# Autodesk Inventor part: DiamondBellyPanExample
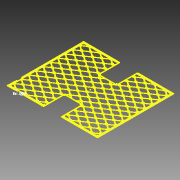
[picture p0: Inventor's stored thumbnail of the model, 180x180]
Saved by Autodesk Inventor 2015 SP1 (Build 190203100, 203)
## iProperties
Created: 2016-01
Part Number: DiamondBellyPanExample
Material: Aluminum 6061
Document SubType Name: Sheet Metal
Designer: User
Density: 2.7 g/cm^3
Sheet Metal Rule: Default
Appearance: Aluminum - Flat
Mass: 806.053 g
Surface Area: 2862.53 cm^2
Volume: 298.538 cm^3
Author: User
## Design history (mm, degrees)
node "Face1"
  sketch "Sketch1"
    geometry: L1 (-330.2, 279.4)-(330.2, 279.4); L2 (330.2, 279.4)-(330.2, -279.4); L3 (330.2, -279.4)-(-330.2, -279.4); L4 (-330.2, -279.4)-(-330.2, 279.4); L5 (-330.2, 279.4)-(330.2, -279.4); L6 (330.2, 279.4)-(-330.2, -279.4); 1 further point
    constraints: 12 end point, 2 midpoint, 2 parallel, 1 horizontal, 1 perpendicular
    dimensions: "d0" = 660.4 distance of L2.end L3.end; "d1" = 558.8 distance of L1.end L2.end
sketch "Sketch2"
  geometry: L1 (-330.2, -279.4)-(-330.2, 279.4) reference; L2 (330.2, -279.4)-(-330.2, -279.4) reference; L3 (330.2, 279.4)-(330.2, -279.4) reference; L4 (-330.2, 279.4)-(330.2, 279.4) reference; L5 (-313.231, -240.03)-(-277.812, -263.831); L6 (-277.812, -263.831)-(-242.394, -240.03); L7 (-242.394, -240.03)-(-277.812, -216.229); L8 (-277.812, -216.229)-(-313.231, -240.03); L9 (-240.26, -238.596)-(-275.678, -214.794); L10 (-238.125, -237.161)-(-273.543, -213.36); L11 (-238.125, -237.161)-(-202.707, -213.36); L12 (-202.707, -213.36)-(-238.125, -189.559); L13 (-238.125, -189.559)-(-273.543, -213.36); L14 (-242.394, -240.03)-(-238.125, -237.161); L15 (-277.812, -216.229)-(-273.543, -213.36); L16 (-313.231, -186.69)-(-277.812, -210.491); L17 (-277.812, -210.491)-(-242.394, -186.69); L18 (-242.394, -186.69)-(-277.812, -162.889); L19 (-277.812, -162.889)-(-313.231, -186.69); L20 (-240.26, -185.256)-(-275.678, -161.454); L21 (-238.125, -183.821)-(-273.543, -160.02); L22 (-238.125, -183.821)-(-202.707, -160.02); L23 (-202.707, -160.02)-(-238.125, -136.219); L24 (-238.125, -136.219)-(-273.543, -160.02); L25 (-242.394, -186.69)-(-238.125, -183.821); L26 (-277.812, -162.889)-(-273.543, -160.02); L27 (-313.231, -133.35)-(-277.812, -157.151); L28 (-277.812, -157.151)-(-242.394, -133.35); L29 (-242.394, -133.35)-(-277.812, -109.549); L30 (-277.812, -109.549)-(-313.231, -133.35); L31 (-240.26, -131.916)-(-275.678, -108.114); L32 (-238.125, -130.481)-(-273.543, -106.68); L33 (-238.125, -130.481)-(-202.707, -106.68); L34 (-202.707, -106.68)-(-238.125, -82.879); L35 (-238.125, -82.879)-(-273.543, -106.68); L36 (-242.394, -133.35)-(-238.125, -130.481); L37 (-277.812, -109.549)-(-273.543, -106.68); L38 (-313.231, -80.01)-(-277.812, -103.811); L39 (-277.812, -103.811)-(-242.394, -80.01); L40 (-242.394, -80.01)-(-277.812, -56.209); L41 (-277.812, -56.209)-(-313.231, -80.01); L42 (-240.26, -78.576)-(-275.678, -54.774); L43 (-238.125, -77.141)-(-273.543, -53.34); L44 (-238.125, -77.141)-(-202.707, -53.34); L45 (-202.707, -53.34)-(-238.125, -29.539); L46 (-238.125, -29.539)-(-273.543, -53.34); L47 (-242.394, -80.01)-(-238.125, -77.141); L48 (-277.812, -56.209)-(-273.543, -53.34); L49 (-313.231, -26.67)-(-277.812, -50.471); L50 (-277.812, -50.471)-(-242.394, -26.67); L51 (-242.394, -26.67)-(-277.812, -2.869); L52 (-277.812, -2.869)-(-313.231, -26.67); L53 (-240.26, -25.236)-(-275.678, -1.434); L54 (-238.125, -23.801)-(-273.543, 0); L55 (-238.125, -23.801)-(-202.707, 0); L56 (-202.707, 0)-(-238.125, 23.801); L57 (-238.125, 23.801)-(-273.543, 0); L58 (-242.394, -26.67)-(-238.125, -23.801); L59 (-277.812, -2.869)-(-273.543, 0); L60 (-313.231, 26.67)-(-277.812, 2.869); L61 (-277.812, 2.869)-(-242.394, 26.67); L62 (-242.394, 26.67)-(-277.812, 50.471); L63 (-277.812, 50.471)-(-313.231, 26.67); L64 (-240.26, 28.104)-(-275.678, 51.906)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; A1 r 2.286 centre (-266.043, -264.414) between (-267.318, -262.517) and (-266.043, -266.7); A2 r 2.286 centre (-210.207, -264.414) between (-210.207, -266.7) and (-208.932, -262.517); A3 r 2.286 centre (-289.582, -264.414) between (-289.582, -266.7) and (-288.307, -262.517); A4 r 2.286 centre (-315.214, -264.414) between (-317.5, -264.414) and (-315.214, -266.7); A5 r 2.286 centre (-315.214, -247.189) between (-313.939, -245.292) and (-317.5, -247.189); A6 r 2.286 centre (-315.214, -232.871) between (-317.5, -232.871) and (-313.939, -234.768); A7 r 2.286 centre (-315.214, -193.849) between (-313.939, -191.952) and (-317.5, -193.849); A8 r 2.286 centre (-238.125, -245.653) between (-236.85, -243.756) and (-239.4, -243.756); A9 r 2.286 centre (-286.18, -213.36) between (-284.905, -215.257) and (-284.905, -211.463); 3 further points
  constraints: 1808 end point, 343 point on line, 18 point on circle, 18 tangent, 9 centre point, 6 equal length, 6 perpendicular, 5 parallel, 4 equal radius, 4 vertical, 2 collinear, 2 horizontal, 2 horizontal alignment, 2 midpoint, 1 vertical alignment, 1683 other
  dimensions: "d15" = 4.7625 distance between parallel lines of L7 L10; "d62" = 53.34 distance of L5.start L16.start (derived); "d69" = 79.375 distance of L6.end L115.end (derived); "d74" = 4.7625 distance between parallel lines of L46 L50 (derived); "d75" = 4.7625 distance between parallel lines of L510 L367 (derived); "d85" = 53.34 distance of L11.end L895.end (derived); "d88" = 79.375 distance of L11.end L898.start (derived); "d91" = 2.286 radius of A1; "d92" = 2.286 radius of A2; "d93" = 2.286 radius of A3; "d94" = 2.286 radius of A8 (derived); "d95" = 2.286 radius of A9 (derived)
cut "Cut1" sketch "Sketch2" dims "d35" = 3.175 (= Thickness), "d36" = 0
feature "Corner Round3" dims "d96" = 2.286
mirror "Mirror3"
mirror "Mirror4"
sketch "Sketch4"
  geometry: L1 (330.2, -279.4)-(-330.2, -279.4) reference; L2 (63.5, -279.4)-(-63.5, -279.4); L3 (-63.5, -279.4)-(-63.5, -127); L4 (-63.5, -127)-(63.5, -127); L5 (63.5, -127)-(63.5, -279.4); 2 further points
  constraints: 8 end point, 2 midpoint, 2 parallel, 1 coincident, 1 horizontal, 1 perpendicular, 1 point on line
  dimensions: "d103" = 152.4 distance between parallel lines of L1 L4 (derived); "d104" = 127 distance between parallel lines of L5 L3 (derived)
cut "Cut2" sketch "Sketch4" dims "d105" = 3.175 (derived), "d106" = 0
node "Face2"
  sketch "Sketch5"
    geometry: L1 (-63.5, -279.4)-(-330.2, -279.4) reference; L2 (-63.5, -279.4)-(-63.5, -127); L3 (-63.5, -127)-(0, -127); L4 (0, -127)-(0, -122.238); L5 (0, -122.238)-(-68.263, -122.238); L6 (-68.263, -122.238)-(-68.262, -279.4); L7 (-63.5, -279.4)-(-68.262, -279.4); 1 further point
    constraints: 12 end point, 4 perpendicular, 2 point on line, 1 collinear, 1 vertical, 1 vertical alignment
    dimensions: "d107" = 63.5 distance from line of point (0, 0) L2 (derived); "d108" = 152.4 distance between parallel lines of L1 L3 (derived); "d109" = 4.7625 distance between parallel lines of L6 L2; "d110" = 4.7625 distance between parallel lines of L5 L3 (derived)
mirror "Mirror5"
feature "Corner Round4" dims "d116" = 4.7625
mirror "Mirror6"
feature "Corner Round5" dims "d117" = 6.35
feature "Corner Round6" dims "d118" = 3.175
sketch "Sketch6"
  geometry: L1 (-330.2, -276.225)-(-330.2, 276.225) reference; L2 (-68.262, -279.4)-(-327.025, -279.4) reference; C1 r 2.451 at (-323.85, -273.05); 5 further points
  constraints: 1 centre point
  dimensions: "d119" = 2.4511 radius of C1; "d120" = 6.35 distance from line of L1 C1.centre; "d121" = 6.35 distance from line of L2 C1.centre (derived)
hole "Hole1" sketch "Sketch6" at (-323.85, -273.05) diameter "d122" = 4.9022 (derived); stored, may be unused: countersink angle "d126" = 82 deg, drill point angle "d128" = 118 deg; dims "d123" = 19.05, "d124" = 9.525, "d125" = 6.35, "d127" = 3.175 (derived)
mirror "Mirror7"
mirror "Mirror8"
sketch "Sketch7"
  geometry: L1 (-330.2, -276.225)-(-330.2, 276.225) reference; L2 (-68.262, -279.4)-(-327.025, -279.4) reference; L3 (-317.5, -232.871)-(-317.5, -193.849) reference; L4 (-210.207, -266.7)-(-266.043, -266.7) reference; L5 (-330.2, -215.9)-(-317.5, -215.9); L6 (-266.7, -279.4)-(-266.7, -266.7); L7 (-315.214, -266.7)-(-266.7, -266.7); L8 (-315.214, -266.7)-(-289.582, -266.7) reference; L9 (-317.5, -264.414)-(-317.5, -215.9); L10 (-274.637, -279.4)-(-266.7, -279.4); L11 (-68.262, -279.4)-(-327.025, -279.4) reference; L12 (-266.7, -271.463)-(-266.7, -279.4); L13 (-330.2, -223.838)-(-330.2, -215.9); L14 (-322.262, -215.9)-(-330.2, -215.9); L15 (-321.27, -213.613)-(-321.27, -191.289); L16 (-322.989, -215.9)-(-330.2, -215.9); L17 (-330.2, -215.9)-(-330.2, -223.838); A1 r 7.938 centre (-274.637, -271.463) between (-274.637, -279.4) and (-266.7, -271.463); A2 r 7.938 centre (-322.262, -223.838) between (-322.262, -215.9) and (-330.2, -223.838); A3 r 2.381 centre (-323.652, -213.613) between (-323.331, -215.972) and (-321.27, -213.613); A4 r 7.938 centre (-322.262, -223.838) between (-323.331, -215.972) and (-330.2, -223.838); A5 r 2.381 centre (-323.652, -213.613) between (-323.331, -215.972) and (-322.989, -215.9); 1 further point
  constraints: 22 end point, 14 tangent, 12 point on circle, 9 point on line, 7 collinear, 5 centre point, 2 perpendicular, 1 horizontal, 1 vertical
  dimensions: "d135" = 63.5 distance between parallel lines of L2 L5 (derived); "d136" = 63.5 distance between parallel lines of L1 L6 (derived); "d137" = 7.9375 radius of A1; "d138" = 7.9375 radius of A2 (derived); "d139" = 3.77031 distance between parallel lines of L3 L15; "d140" = 2.38125 radius of A3
cut "Cut3" sketch "Sketch7" dims "d141" = 3.175 (derived), "d142" = 0
workplane "Work Plane1"
mirror "Mirror9"
sketch "Sketch8"
  geometry: L1 (-266.7, -272.189)-(-266.7, -279.4) reference; L2 (-68.262, -279.4)-(-266.7, -279.4) reference; L3 (-264.413, -270.47)-(-229.455, -270.47); L4 (-222.25, -277.882)-(-222.25, -279.4); L5 (-266.7, -272.189)-(-266.7, -279.4); L6 (-266.7, -279.4)-(-222.25, -279.4); L7 (-222.25, -279.4)-(-266.7, -279.4); L8 (-266.7, -279.4)-(-266.7, -272.189); C1 r 2.451 at (-260.35, -273.05) reference; C2 r 2.451 at (-247.65, -273.05) reference; C3 r 2.451 at (-234.95, -273.05) reference; C4 r 2.451 at (-222.25, -273.05) reference; C5 r 2.451 at (-222.25, -273.05); A1 r 2.381 centre (-264.413, -272.852) between (-266.7, -272.189) and (-266.772, -272.531) reference; A2 r 2.381 centre (-264.413, -272.852) between (-264.413, -270.47) and (-266.772, -272.531); A3 r 2.381 centre (-229.455, -272.852) between (-227.082, -273.05) and (-229.455, -270.47); A4 r 4.832 centre (-222.25, -273.05) between (-227.082, -273.05) and (-222.25, -277.882); A5 r 2.381 centre (-264.413, -272.852) between (-264.413, -270.47) and (-266.7, -272.189); 1 further point
  constraints: 12 end point, 8 point on circle, 5 centre point, 4 tangent, 3 collinear, 2 horizontal alignment, 2 perpendicular, 1 coincident, 1 concentric, 1 horizontal, 1 point on line
  dimensions: "d144" = 2.38125 radius of A3 (derived); "d147" = 38.1 distance of C1.centre A4.centre (derived); "d148" = 2.4511 radius of C5 (derived); "d149" = 2.38125 radial gap between concentric circles of A4 C5; "d150" = 38.1 horizontal distance of C1.centre L4.start (derived)
cut "Cut4" sketch "Sketch8" dims "d145" = 3.175 (derived), "d146" = 0
mirror "Mirror10"
sketch "Sketch9"
  geometry: L1 (-330.2, -276.225)-(-330.2, -223.838) reference; L2 (-274.637, -279.4)-(-327.025, -279.4) reference; L3 (-264.413, -270.47)-(-229.455, -270.47) reference; L4 (-222.25, -277.882)-(-222.25, -279.4) reference; L5 (-68.262, -279.4)-(-222.25, -279.4) reference; L6 (-63.5, -274.637)-(-63.5, -131.763) reference; L7 (-58.738, -127)-(58.737, -127) reference; L8 (63.5, -131.763)-(63.5, -274.638) reference; L9 (327.025, -279.4)-(68.263, -279.4) reference; L10 (330.2, 276.225)-(330.2, -276.225) reference; L11 (69.85, 279.4)-(327.025, 279.4) reference; L12 (63.5, 273.05)-(63.5, 131.763) reference; L13 (-58.738, 127)-(58.737, 127) reference; L14 (-63.5, 131.763)-(-63.5, 273.05) reference; L15 (-327.025, 279.4)-(-69.85, 279.4) reference; L16 (-330.2, -171.45)-(-330.2, 276.225) reference; L17 (-330.2, -171.45)-(-328.682, -171.45) reference; L18 (-321.27, -178.655)-(-321.27, -213.613) reference; L19 (-12.267, 122.238)-(12.267, 122.238) reference; L20 (12.267, 122.238)-(32.595, 108.577) reference; L21 (32.595, 104.783)-(1.275, 83.736) reference; L22 (-1.275, 83.736)-(-32.595, 104.783) reference; L23 (-32.595, 108.577)-(-12.267, 122.238) reference; L24 (68.262, 266.7)-(107.293, 266.7) reference; L25 (108.568, 262.517)-(80.65, 243.756) reference; L26 (78.1, 243.756)-(68.262, 250.367) reference; L27 (68.262, 250.367)-(68.262, 266.7) reference; L28 (20.806, 122.238)-(58.569, 122.238) reference; L29 (58.569, 122.238)-(40.963, 110.406) reference; L30 (38.412, 110.406)-(20.806, 122.238) reference; L31 (68.262, 244.629)-(72.282, 241.927) reference; L32 (72.282, 238.133)-(68.262, 235.431) reference; L33 (68.262, 235.431)-(68.262, 244.629) reference; L34 (68.262, 229.693)-(78.1, 236.304) reference; L35 (80.65, 236.304)-(111.97, 215.257) reference; L36 (111.97, 211.463)-(80.65, 190.416) reference; L37 (78.1, 190.416)-(68.263, 197.027) reference; L38 (68.263, 197.027)-(68.262, 229.693) reference; L39 (68.263, 191.289)-(72.282, 188.587) reference; L40 (72.282, 184.793)-(68.263, 182.091) reference; L41 (68.263, 182.091)-(68.263, 191.289) reference; L42 (68.263, 176.353)-(78.1, 182.964) reference; L43 (80.65, 182.964)-(111.97, 161.917) reference; L44 (111.97, 158.123)-(80.65, 137.076) reference; L45 (78.1, 137.076)-(68.263, 143.687) reference; L46 (68.263, 143.687)-(68.263, 176.353) reference; L47 (68.263, 128.751)-(68.263, 137.949) reference; L48 (68.263, 137.949)-(72.282, 135.247) reference; L49 (72.282, 131.453)-(68.263, 128.751) reference; L50 (12.267, -122.238)-(-12.267, -122.238) reference; L51 (-12.267, -122.238)-(-32.595, -108.577) reference; L52 (-32.595, -104.783)-(-1.275, -83.736) reference; L53 (1.275, -83.736)-(32.595, -104.783) reference; L54 (32.595, -108.577)-(12.267, -122.238) reference; L55 (20.806, -122.238)-(38.412, -110.406) reference; L56 (40.963, -110.406)-(58.569, -122.238) reference; L57 (20.806, -122.238)-(58.569, -122.238) reference; L58 (68.263, -128.751)-(72.282, -131.453) reference; L59 (72.282, -135.247)-(68.263, -137.949) reference; L60 (68.263, -128.751)-(68.263, -137.949) reference; L61 (68.263, -143.687)-(78.1, -137.076) reference; L62 (80.65, -137.076)-(111.97, -158.123) reference; L63 (111.97, -161.917)-(80.65, -182.964) reference; L64 (78.1, -182.964)-(68.263, -176.353) reference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; C1 r 2.451 at (-323.85, -273.05) reference; C2 r 2.451 at (-323.85, -260.35) reference; C3 r 2.451 at (-323.85, -247.65) reference; C4 r 2.451 at (-323.85, -234.95) reference; C5 r 2.451 at (-323.85, -222.25) reference; C6 r 2.451 at (-323.85, -171.45) reference; C7 r 2.451 at (-323.85, -158.75) reference; C8 r 2.451 at (-323.85, -146.05) reference; C9 r 2.451 at (-323.85, -133.35) reference; C10 r 2.451 at (-323.85, -120.65) reference; C11 r 2.451 at (-323.85, -107.95) reference; C12 r 2.451 at (-323.85, -95.25) reference; C13 r 2.451 at (-323.85, -82.55) reference; C14 r 2.451 at (-323.85, -69.85) reference; C15 r 2.451 at (-323.85, -57.15) reference; C16 r 2.451 at (-323.85, -44.45) reference; C17 r 2.451 at (-323.85, -31.75) reference; C18 r 2.451 at (-323.85, -19.05) reference; C19 r 2.451 at (-323.85, -6.35) reference; C20 r 2.451 at (-311.15, -273.05) reference; C21 r 2.451 at (-298.45, -273.05) reference; C22 r 2.451 at (-285.75, -273.05) reference; C23 r 2.451 at (-273.05, -273.05) reference; C24 r 2.451 at (-222.25, -273.05) reference; C25 r 2.451 at (-209.55, -273.05) reference; C26 r 2.451 at (-196.85, -273.05) reference; C27 r 2.451 at (-184.15, -273.05) reference; C28 r 2.451 at (-171.45, -273.05) reference; C29 r 2.451 at (-158.75, -273.05) reference; C30 r 2.451 at (-146.05, -273.05) reference; C31 r 2.451 at (-133.35, -273.05) reference; C32 r 2.451 at (-120.65, -273.05) reference; C33 r 2.451 at (-107.95, -273.05) reference; C34 r 2.451 at (-95.25, -273.05) reference; C35 r 2.451 at (-82.55, -273.05) reference; C36 r 2.451 at (-69.85, -273.05) reference; C37 r 2.451 at (-323.85, 273.05) reference; C38 r 2.451 at (-323.85, 260.35) reference; C39 r 2.451 at (-323.85, 247.65) reference; C40 r 2.451 at (-323.85, 234.95) reference; C41 r 2.451 at (-323.85, 222.25) reference; C42 r 2.451 at (-323.85, 209.55) reference; C43 r 2.451 at (-323.85, 196.85) reference; C44 r 2.451 at (-323.85, 184.15) reference; C45 r 2.451 at (-323.85, 171.45) reference; C46 r 2.451 at (-323.85, 158.75) reference; C47 r 2.451 at (-323.85, 146.05) reference; C48 r 2.451 at (-323.85, 133.35) reference; C49 r 2.451 at (-323.85, 120.65) reference; C50 r 2.451 at (-323.85, 107.95) reference; C51 r 2.451 at (-323.85, 95.25) reference; C52 r 2.451 at (-323.85, 82.55) reference; C53 r 2.451 at (-323.85, 69.85) reference; C54 r 2.451 at (-323.85, 57.15) reference; C55 r 2.451 at (-323.85, 44.45) reference; C56 r 2.451 at (-323.85, 31.75) reference; C57 r 2.451 at (-323.85, 19.05) reference; C58 r 2.451 at (-323.85, 6.35) reference; C59 r 2.451 at (-311.15, 273.05) reference; C60 r 2.451 at (-298.45, 273.05) reference; C61 r 2.451 at (-285.75, 273.05) reference; C62 r 2.451 at (-273.05, 273.05) reference; C63 r 2.451 at (-260.35, 273.05) reference; C64 r 2.451 at (-247.65, 273.05) reference; A1 r 2.381 centre (-323.652, -213.613) between (-323.331, -215.972) and (-321.27, -213.613) reference; A2 r 7.938 centre (-322.262, -223.838) between (-323.331, -215.972) and (-330.2, -223.838) reference; A3 r 3.175 centre (-327.025, -276.225) between (-330.2, -276.225) and (-327.025, -279.4) reference; A4 r 7.938 centre (-274.638, -271.462) between (-274.637, -279.4) and (-266.772, -272.531) reference; A5 r 2.381 centre (-264.413, -272.852) between (-264.413, -270.47) and (-266.772, -272.531) reference; A6 r 2.381 centre (-229.455, -272.852) between (-227.082, -273.05) and (-229.455, -270.47) reference; A7 r 4.832 centre (-222.25, -273.05) between (-227.082, -273.05) and (-222.25, -277.882) reference; A8 r 4.763 centre (-68.262, -274.637) between (-68.262, -279.4) and (-63.5, -274.637) reference; A9 r 4.763 centre (-58.738, -131.763) between (-58.738, -127) and (-63.5, -131.763) reference; A10 r 4.763 centre (58.738, -131.763) between (63.5, -131.763) and (58.737, -127) reference; A11 r 4.763 centre (68.263, -274.638) between (63.5, -274.638) and (68.263, -279.4) reference; A12 r 3.175 centre (327.025, -276.225) between (327.025, -279.4) and (330.2, -276.225) reference; A13 r 3.175 centre (327.025, 276.225) between (330.2, 276.225) and (327.025, 279.4) reference; A14 r 6.35 centre (69.85, 273.05) between (69.85, 279.4) and (63.5, 273.05) reference; A15 r 4.763 centre (58.738, 131.763) between (58.737, 127) and (63.5, 131.763) reference; A16 r 4.763 centre (-58.738, 131.763) between (-63.5, 131.763) and (-58.738, 127) reference; A17 r 6.35 centre (-69.85, 273.05) between (-63.5, 273.05) and (-69.85, 279.4) reference; A18 r 3.175 centre (-327.025, 276.225) between (-327.025, 279.4) and (-330.2, 276.225) reference; A19 r 4.832 centre (-323.85, -171.45) between (-328.682, -171.45) and (-323.85, -176.282) reference; A20 r 2.381 centre (-323.652, -178.655) between (-321.27, -178.655) and (-323.85, -176.282) reference; A21 r 2.286 centre (31.32, 106.68) between (32.595, 104.783) and (32.595, 108.577) reference; A22 r 2.286 centre (0, 85.633) between (-1.275, 83.736) and (1.275, 83.736) reference; A23 r 2.286 centre (-31.32, 106.68) between (-32.595, 108.577) and (-32.595, 104.783) reference; A24 r 2.286 centre (107.293, 264.414) between (108.568, 262.517) and (107.293, 266.7) reference; A25 r 2.286 centre (79.375, 245.653) between (78.1, 243.756) and (80.65, 243.756) reference; A26 r 2.286 centre (39.687, 112.303) between (38.412, 110.406) and (40.963, 110.406) reference; A27 r 2.286 centre (71.007, 240.03) between (72.282, 238.133) and (72.282, 241.927) reference; A28 r 2.286 centre (79.375, 234.407) between (80.65, 236.304) and (78.1, 236.304) reference; A29 r 2.286 centre (110.695, 213.36) between (111.97, 211.463) and (111.97, 215.257) reference; A30 r 2.286 centre (79.375, 192.313) between (78.1, 190.416) and (80.65, 190.416) reference; A31 r 2.286 centre (71.007, 186.69) between (72.282, 184.793) and (72.282, 188.587) reference; A32 r 2.286 centre (79.375, 181.067) between (80.65, 182.964) and (78.1, 182.964) reference; A33 r 2.286 centre (110.695, 160.02) between (111.97, 158.123) and (111.97, 161.917) reference; A34 r 2.286 centre (79.375, 138.973) between (78.1, 137.076) and (80.65, 137.076) reference; A35 r 2.286 centre (71.007, 133.35) between (72.282, 131.453) and (72.282, 135.247) reference; A36 r 2.286 centre (-31.32, -106.68) between (-32.595, -104.783) and (-32.595, -108.577) reference; A37 r 2.286 centre (0, -85.633) between (1.275, -83.736) and (-1.275, -83.736) reference; A38 r 2.286 centre (31.32, -106.68) between (32.595, -108.577) and (32.595, -104.783) reference; A39 r 2.286 centre (39.687, -112.303) between (40.963, -110.406) and (38.412, -110.406) reference; A40 r 2.286 centre (71.007, -133.35) between (72.282, -135.247) and (72.282, -131.453) reference; A41 r 2.286 centre (79.375, -138.973) between (80.65, -137.076) and (78.1, -137.076) reference; A42 r 2.286 centre (110.695, -160.02) between (111.97, -161.917) and (111.97, -158.123) reference; A43 r 2.286 centre (79.375, -181.067) between (78.1, -182.964) and (80.65, -182.964) reference; A44 r 2.286 centre (71.007, -186.69) between (72.282, -188.587) and (72.282, -184.793) reference; A45 r 2.286 centre (79.375, -192.313) between (80.65, -190.416) and (78.1, -190.416) reference; A46 r 2.286 centre (110.695, -213.36) between (111.97, -215.257) and (111.97, -211.463) reference; A47 r 2.286 centre (79.375, -234.407) between (78.1, -236.304) and (80.65, -236.304) reference; A48 r 2.286 centre (71.007, -240.03) between (72.282, -241.927) and (72.282, -238.133) reference; A49 r 2.286 centre (0, 21.047) between (1.275, 22.944) and (-1.275, 22.944) reference; A50 r 2.286 centre (31.32, 0) between (32.595, -1.897) and (32.595, 1.897) reference; A51 r 2.286 centre (0, -21.047) between (-1.275, -22.944) and (1.275, -22.944) reference; A52 r 2.286 centre (-31.32, 0) between (-32.595, 1.897) and (-32.595, -1.897) reference; A53 r 2.286 centre (39.687, 47.717) between (40.963, 49.614) and (38.412, 49.614) reference; A54 r 2.286 centre (71.007, 26.67) between (72.282, 24.773) and (72.282, 28.567) reference; A55 r 2.286 centre (39.687, 5.623) between (38.412, 3.726) and (40.963, 3.726) reference; A56 r 2.286 centre (8.368, 26.67) between (7.093, 28.567) and (7.093, 24.773) reference; A57 r 2.286 centre (0, 74.387) between (1.275, 76.284) and (-1.275, 76.284) reference; A58 r 2.286 centre (31.32, 53.34) between (32.595, 51.443) and (32.595, 55.237) reference; A59 r 2.286 centre (0, 32.293) between (-1.275, 30.396) and (1.275, 30.396) reference; A60 r 2.286 centre (-31.32, 53.34) between (-32.595, 55.237) and (-32.595, 51.443) reference; A61 r 2.286 centre (39.687, 101.057) between (40.963, 102.954) and (38.412, 102.954) reference; A62 r 2.286 centre (71.007, 80.01) between (72.282, 78.113) and (72.282, 81.907) reference; A63 r 2.286 centre (39.687, 58.963) between (38.412, 57.066) and (40.963, 57.066) reference; A64 r 2.286 centre (8.368, 80.01) between (7.093, 81.907) and (7.093, 78.113) reference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; 1 further point
  constraints: 1 centre point
  dimensions: "d151" = 2.4511 diameter of C163 (derived)
body "Solid1"
pattern_linear "Rectangular Pattern3" dims "d99" = 53.34 (derived), "d102" = 79.375 (derived)
pattern_linear "Rectangular Pattern4" dims "d131" = 12.7 (derived)
pattern_linear "Rectangular Pattern5" dims "d134" = 12.7 (derived)
face "Plate1" dims "Thickness" = 3.175
node "Projected Loop1"
face "Plate2" dims "d111" = 3.175 (derived), "d112" = 3.175 (derived), "d114" = 6.35 (derived), "Thickness" = 3.175
bend "Bend1" dims "d111" = 3.175 (derived), "d112" = 3.175 (derived), "d113" = 1.5875 (derived), "d114" = 6.35 (derived), "d115" = 3.175 (derived), "SeamGap" = 0.00508, "Thickness" = 3.175
other parameters: "BendRadius" = 3.175 (= Thickness), "BendReliefWidth" = 3.175 (= Thickness), "BendReliefDepth" = 1.5875 (= 0.5 x Thickness), "CornerReliefSize" = 12.7 (= 4 x Thickness), "MinimumRemnant" = 6.35 (= 2 x Thickness), "TransitionRadius" = 3.175 (= BendRadius), "JacobiRadiusSize" = 3.175 (= BendRadius), "GapSize" = 3.175 (= Thickness), "d2" = 3.175 (= BendRadius), "d15" = 4.7625, "DistX" = 53.34 [user parameter], "DistY" = 79.375 [user parameter], "EdgeThicknessX" = 12.7 [user parameter], "EdgeThicknessY" = 12.7 [user parameter], "d62" = 53.34 (derived), "d65" = 25.4, "d69" = 79.375 (derived), "d72" = 25.4, "d74" = 4.7625 (derived), "d75" = 4.7625 (derived), "d85" = 53.34 (derived), "d88" = 79.375 (derived), "d91" = 2.286, "d92" = 2.286, "d93" = 2.286, "d94" = 2.286 (derived), "d95" = 2.286 (derived), "GearBoxWidth" = 127 [user parameter], "GearBoxLength" = 152.4 [user parameter], "RivetDiameter" = 4.9022 [user parameter], "GussetLegLength" = 63.5 [user parameter], "HoleSpacing" = 12.7 [user parameter], "d143" = 2.38125, "d151" = 2.4511 (derived)
